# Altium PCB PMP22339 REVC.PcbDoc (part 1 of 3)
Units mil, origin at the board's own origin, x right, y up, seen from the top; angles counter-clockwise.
Board outline 4555 x 3750 mil, 4 copper layers (Top Layer, Signal Layer 2, Signal Layer 3, Bottom Layer), stack 62.6 mil thick; 180 components, 83 nets, 384 pads, 132 vias.
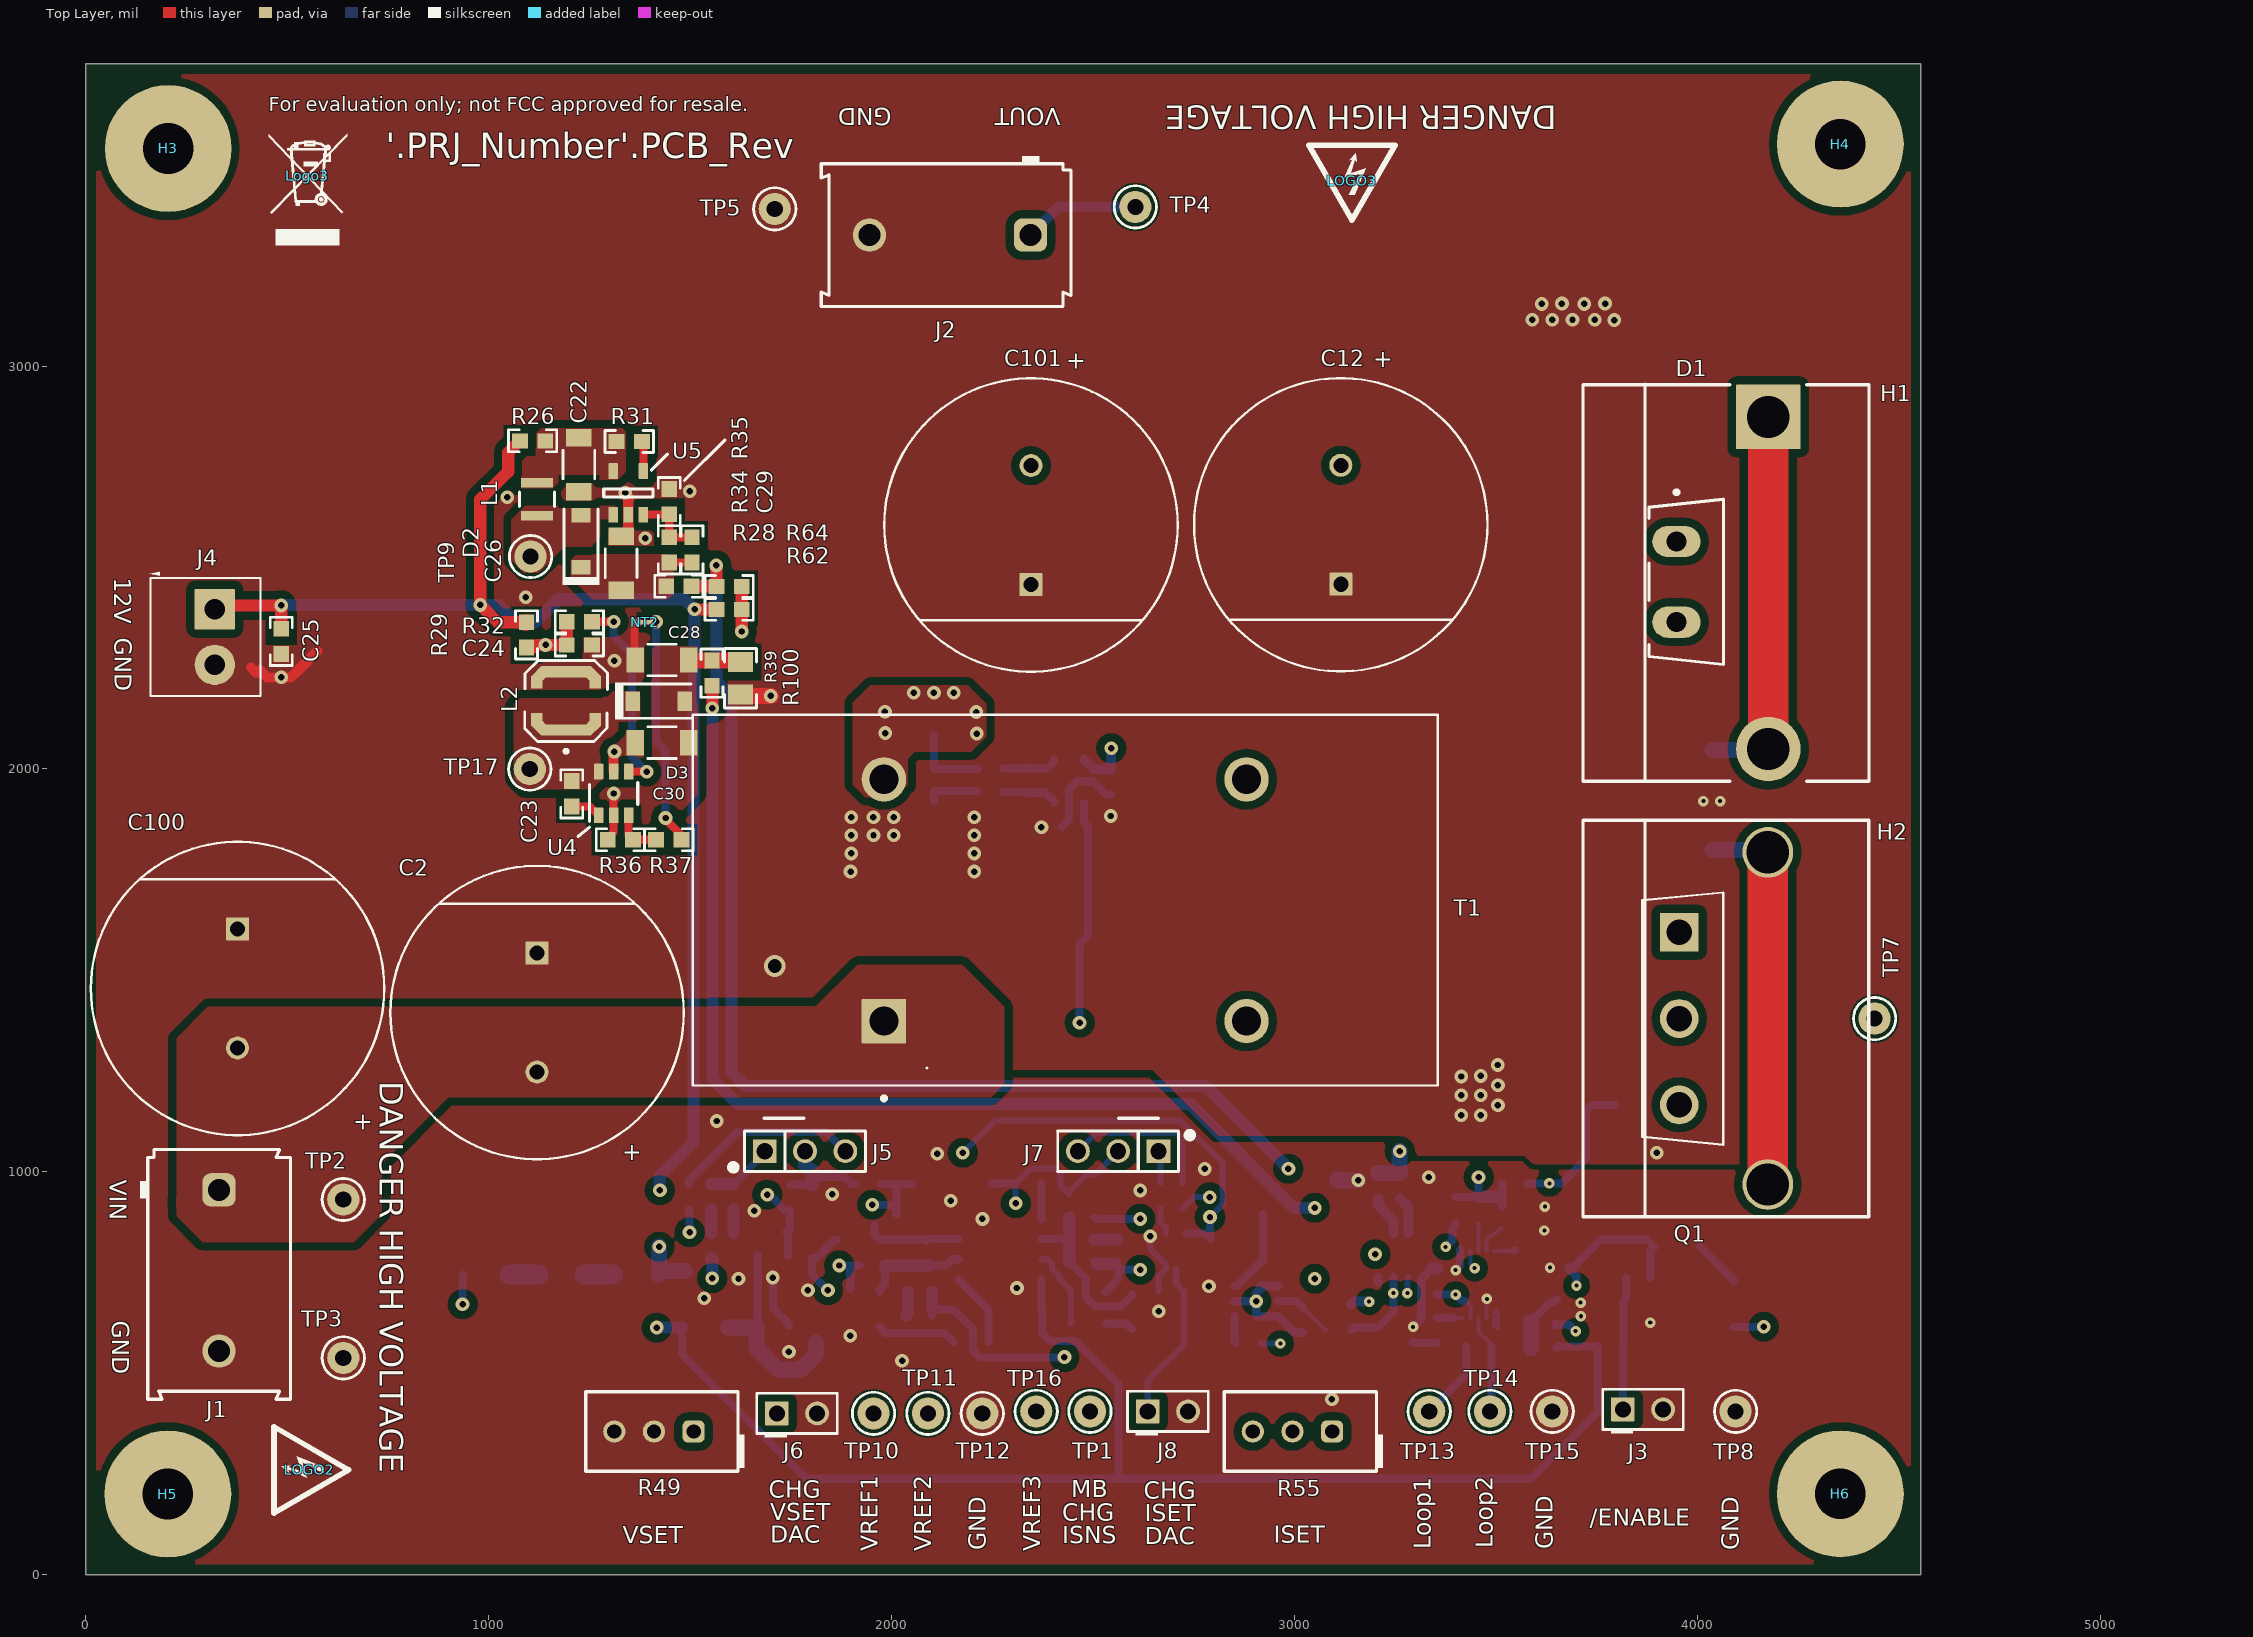
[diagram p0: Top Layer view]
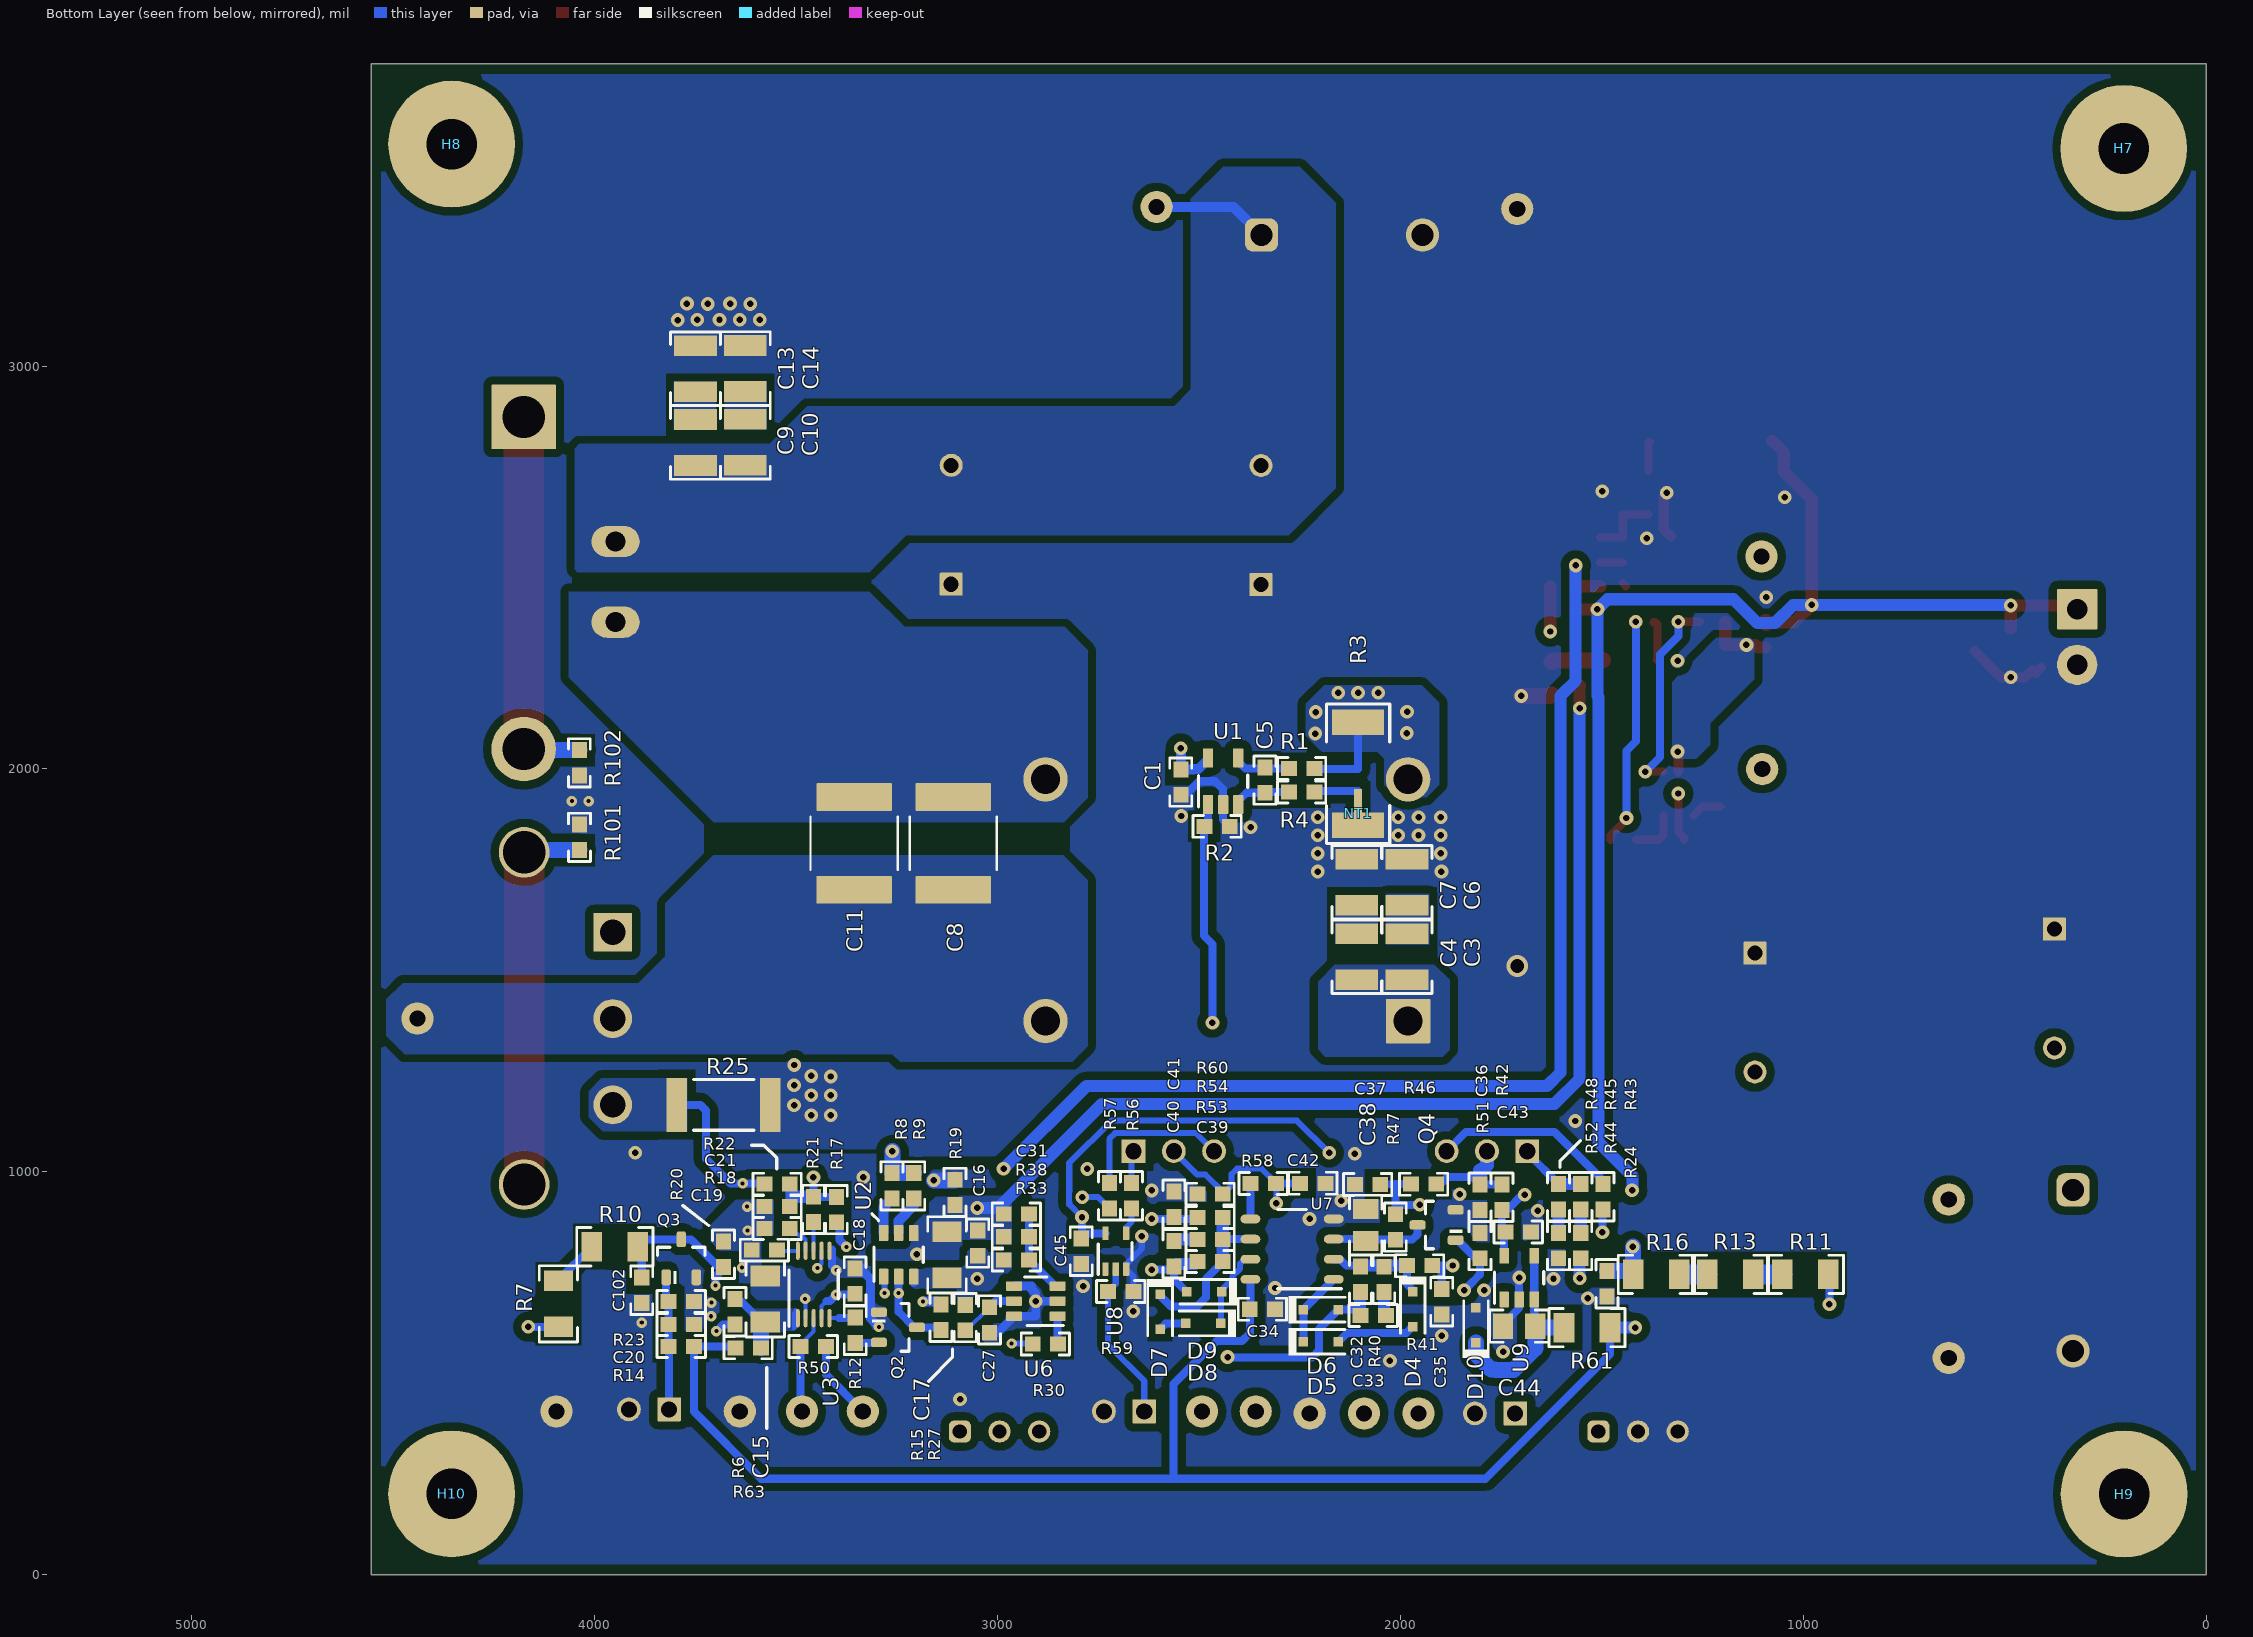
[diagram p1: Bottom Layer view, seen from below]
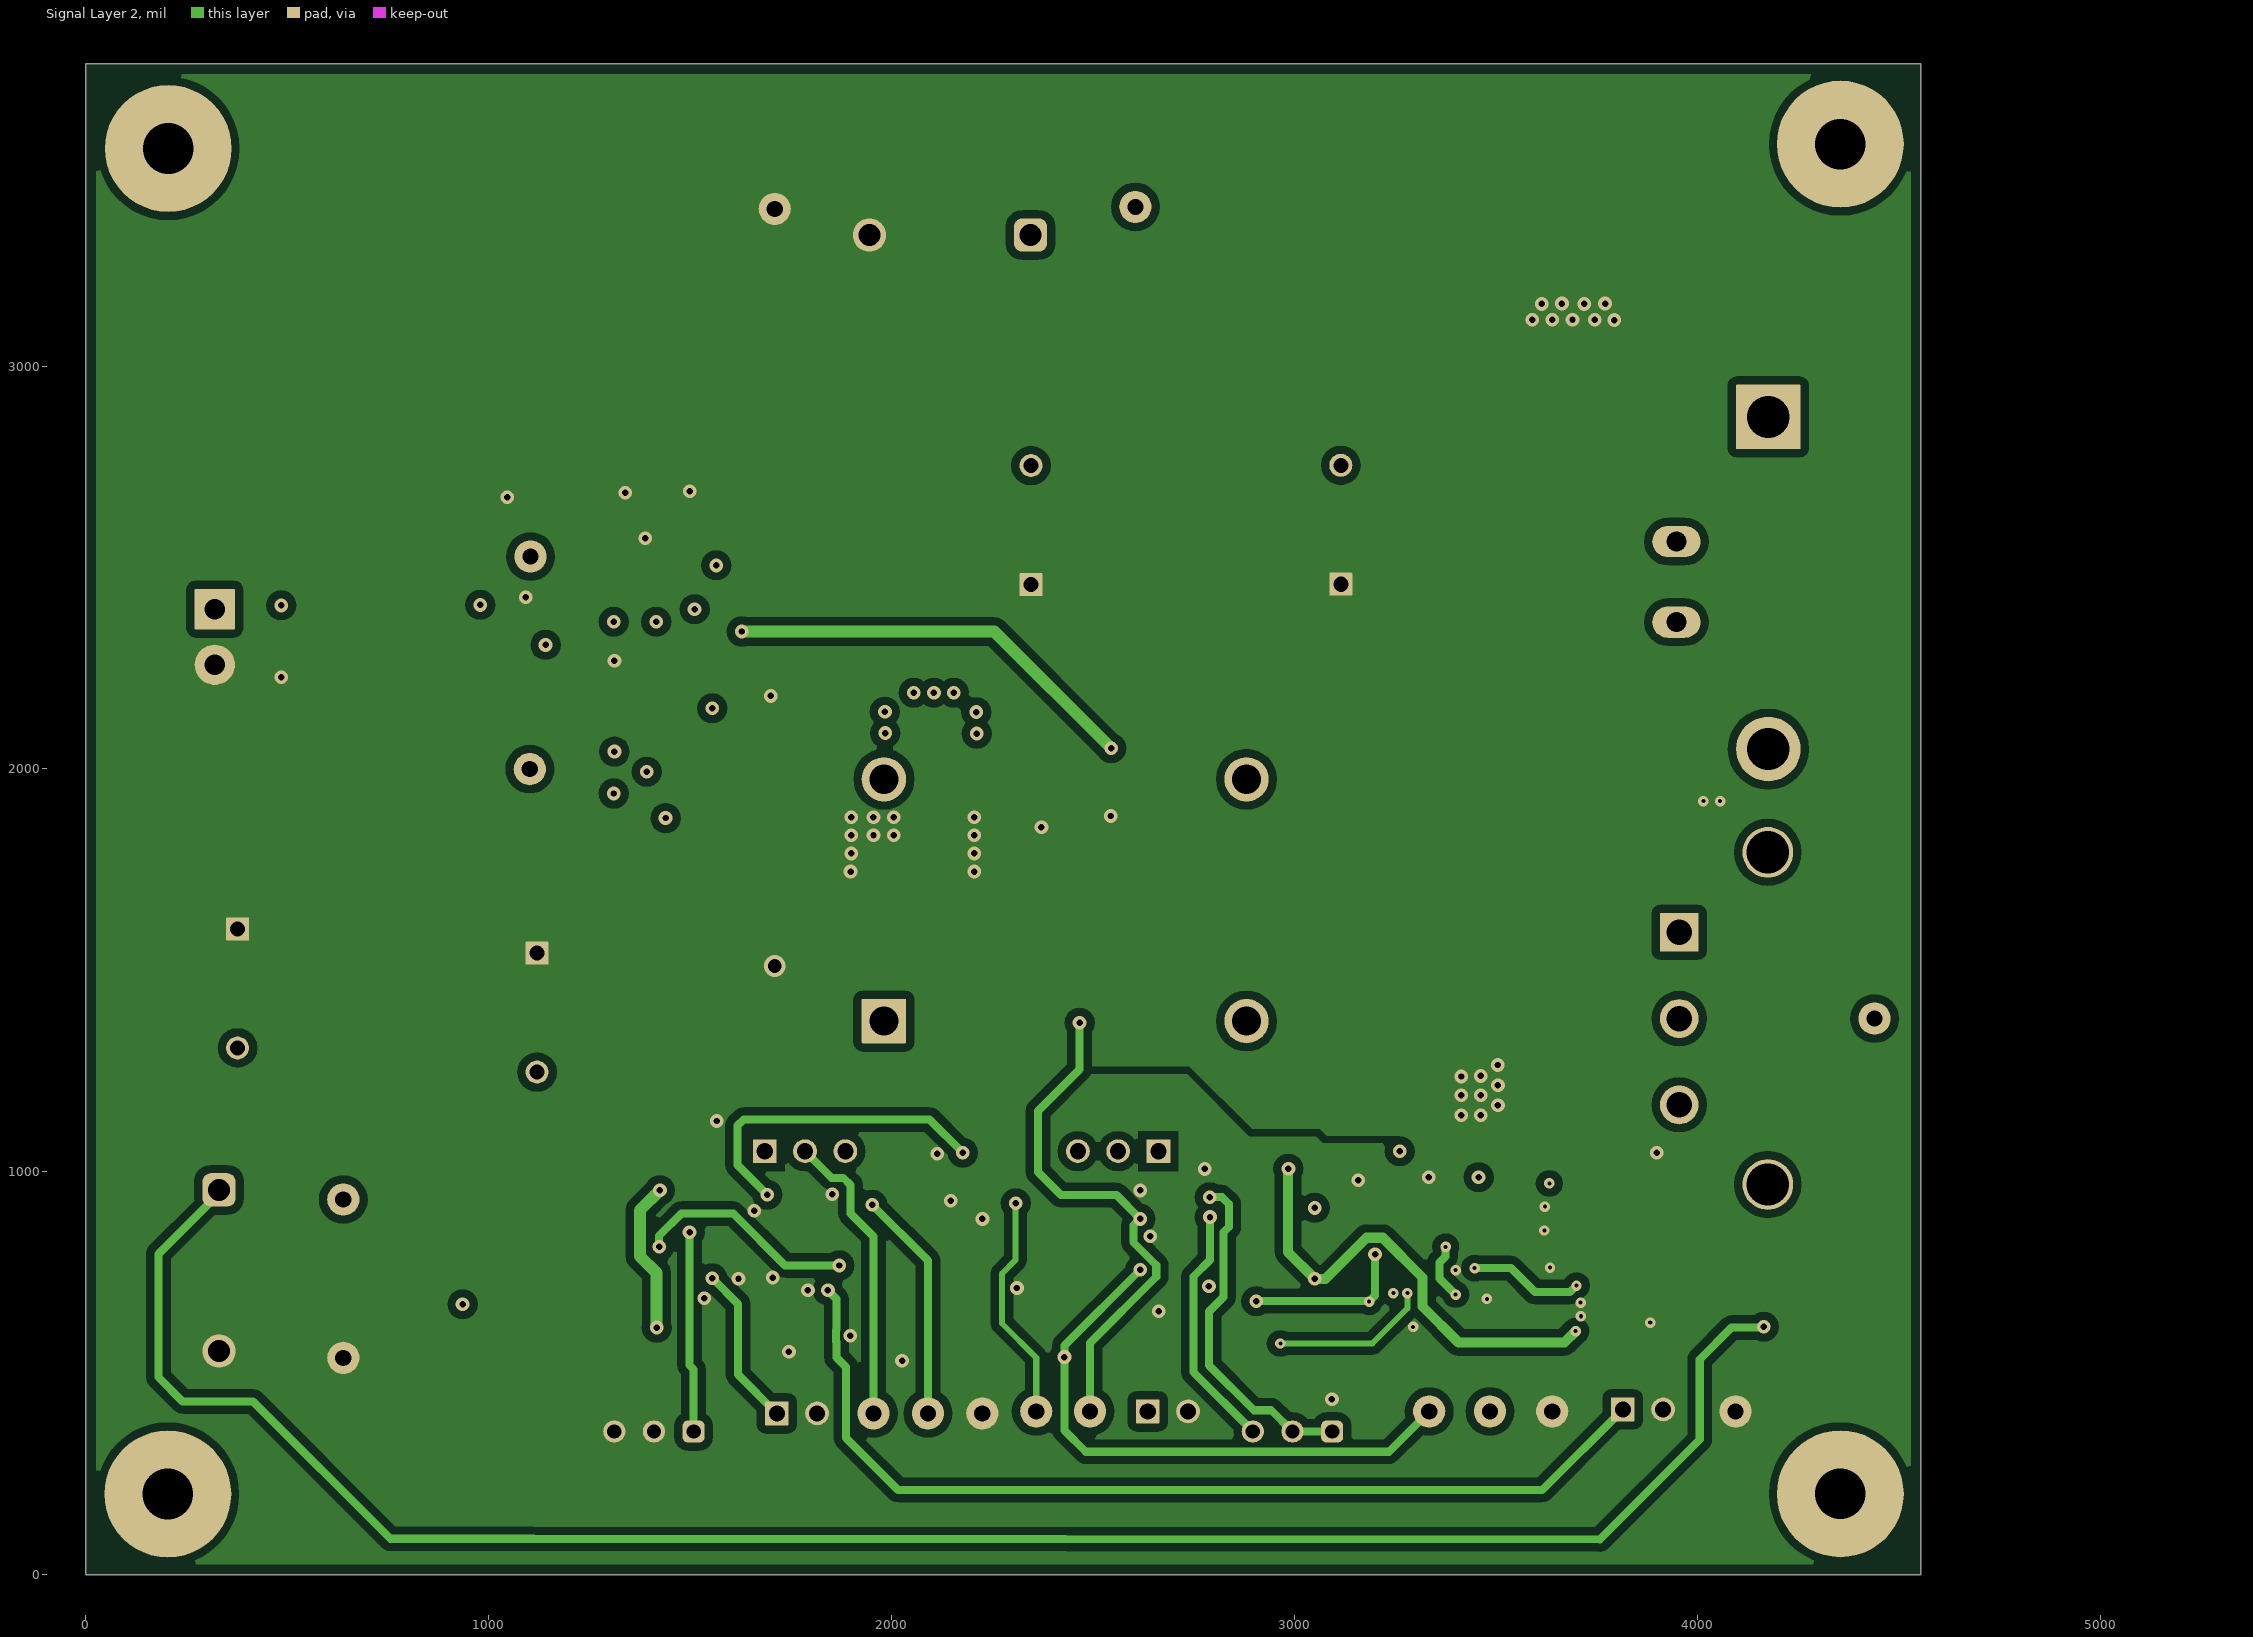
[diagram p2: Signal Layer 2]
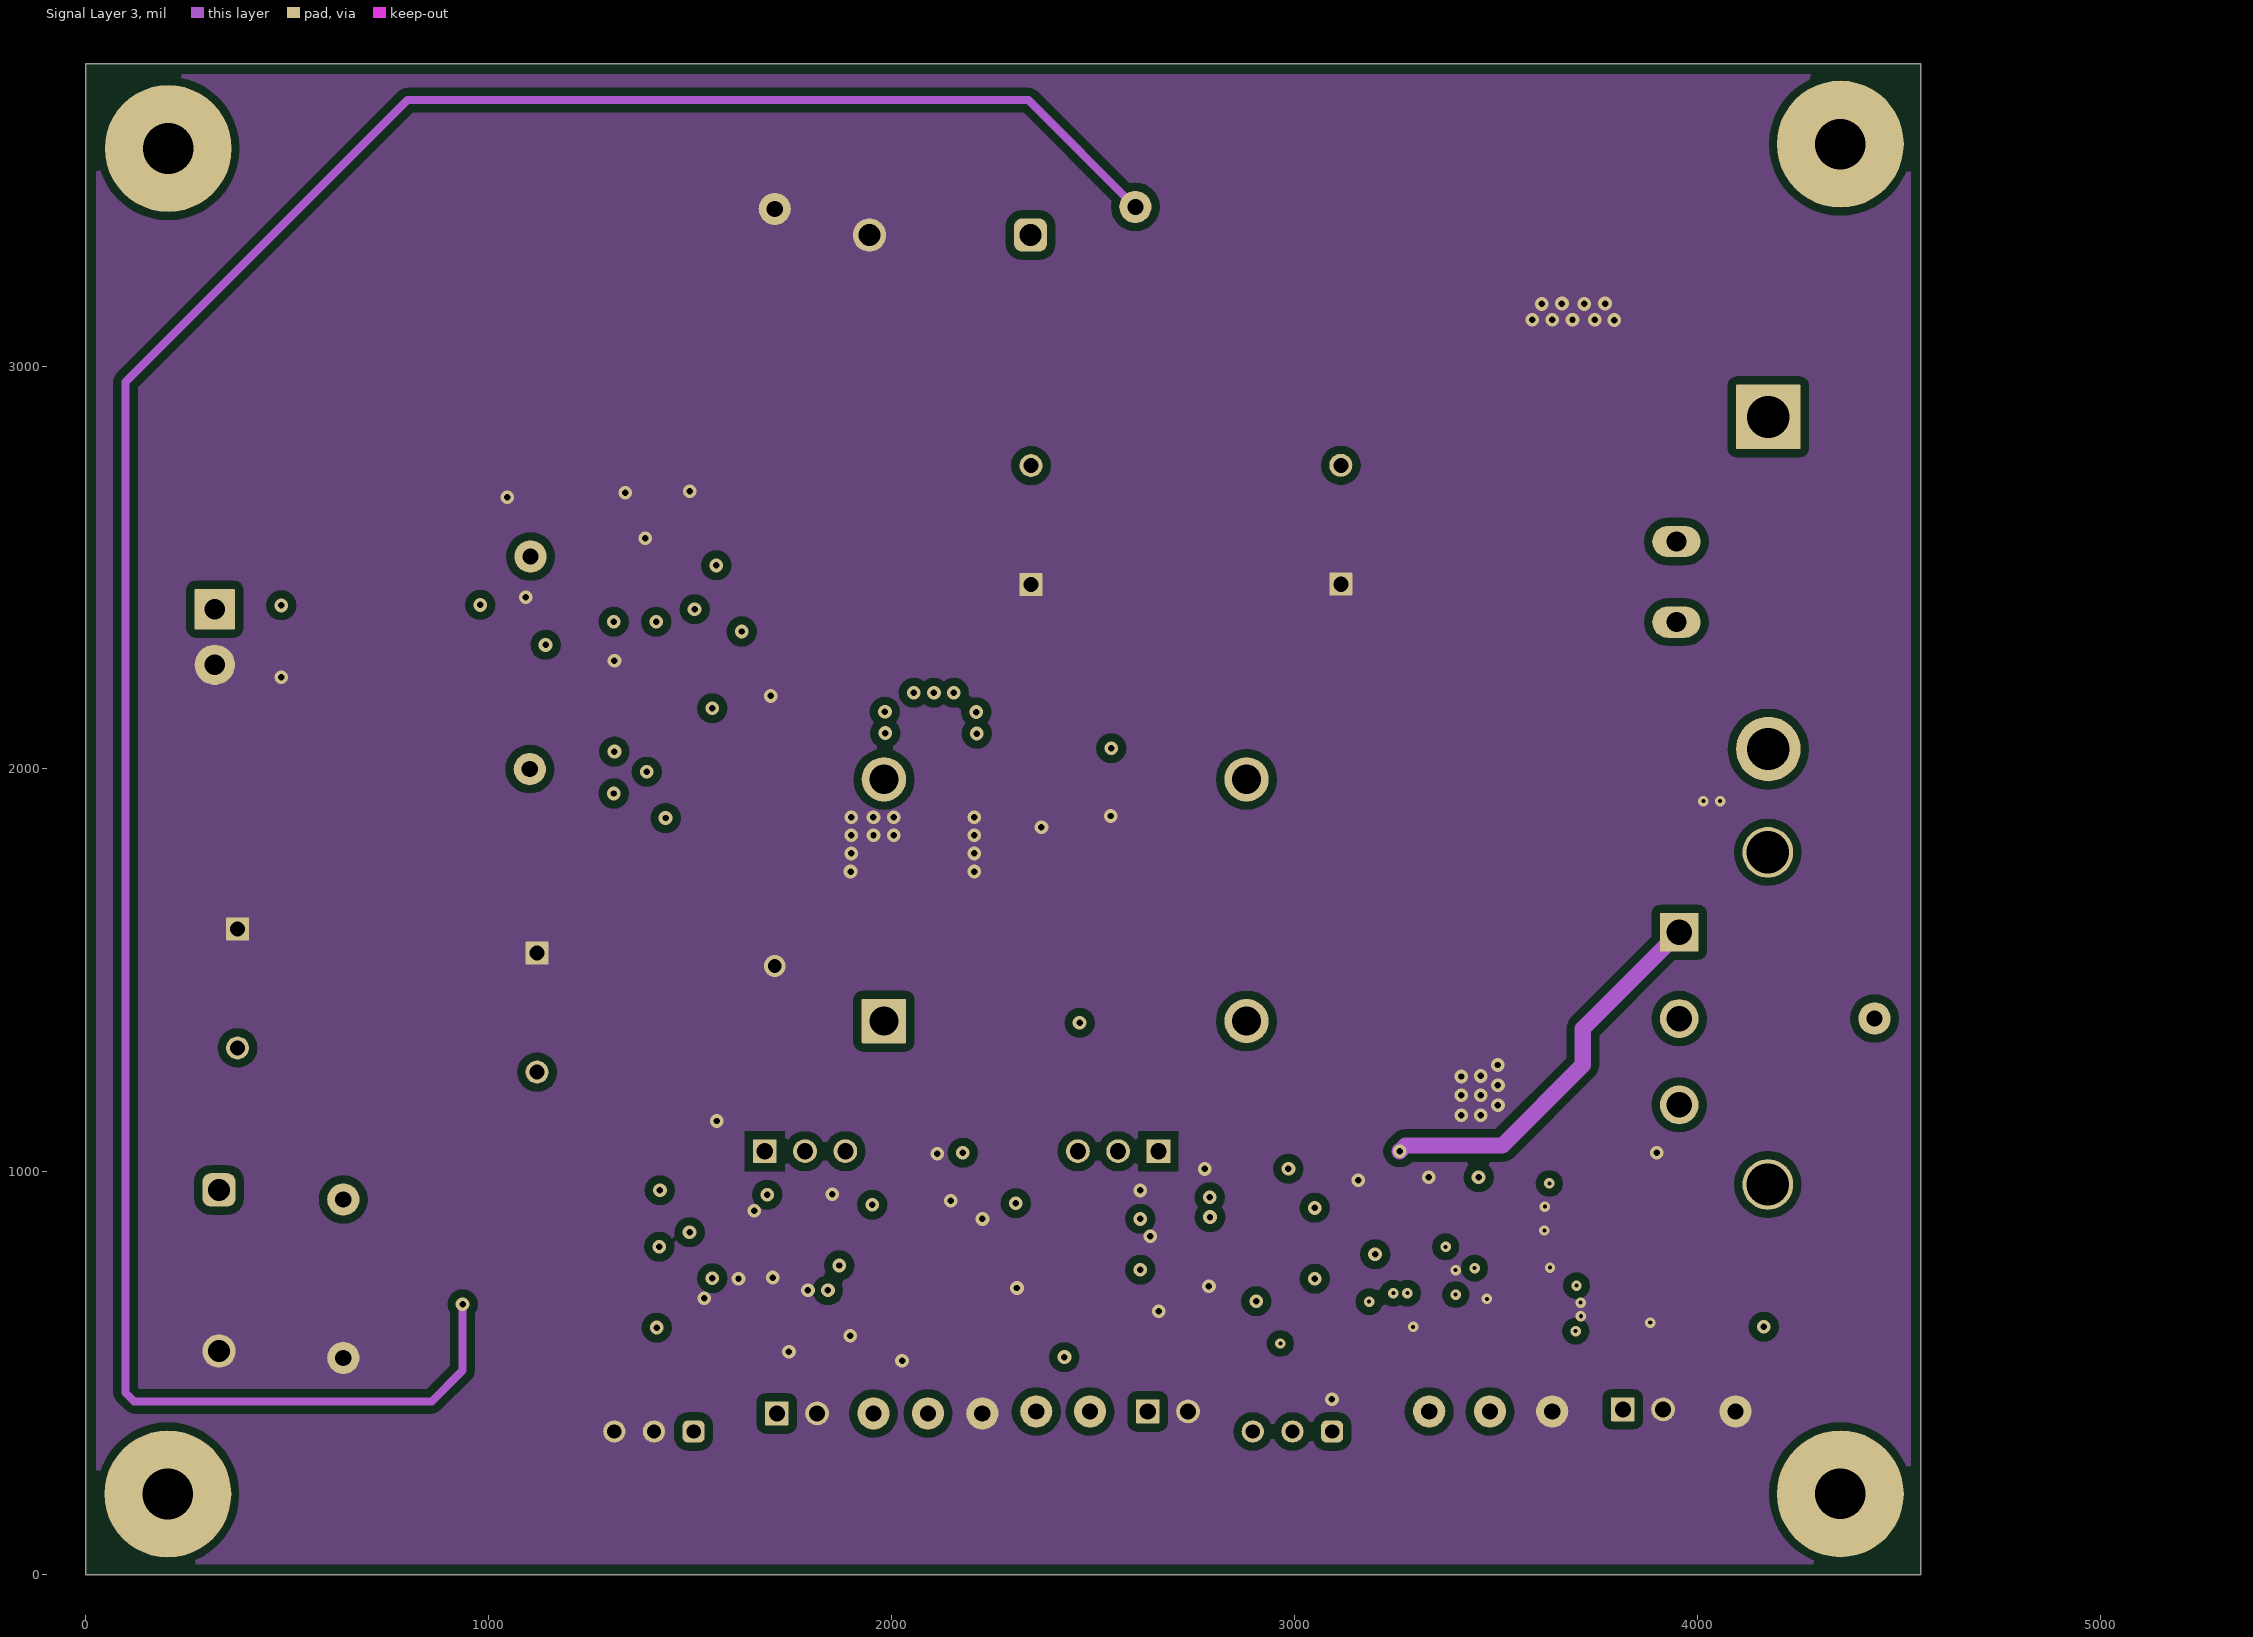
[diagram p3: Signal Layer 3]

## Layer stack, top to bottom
Top Solder: solder mask 0.4, Solder Resist, Dk 3.5
Top Layer: signal copper 2.4
Dielectric1: core 18, FR-4, Dk 4.8
Signal Layer 2: signal copper 2.4
Dielectric 2: prepreg 17, Dk 4.2
Signal Layer 3: signal copper 2.4
Dielectric 3: core 18, Dk 4.2
Bottom Layer: signal copper 2.4
Bottom Solder: solder mask 0.4, Solder Resist, Dk 3.5

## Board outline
0,0 0,3750 4555,3750 4555,0

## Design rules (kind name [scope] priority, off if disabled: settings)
AcuteAngle [All] p1: minimum=4.50000000000000E+0001 checktracksonly=FALSE
AssemblyTestPointUsage [All] p1: valid=2
BoardOutlineClearance BoardOutlineClearance_MountingHoles [OnCopper and InComponentClass('Mounting Holes')] p1: gap=39.37 ignorepadtopadclearanceinfootprint=FALSE
BoardOutlineClearance BoardOutlineClearance_Poly [OnCopper and IsPoly] p2: gap=25 ignorepadtopadclearanceinfootprint=FALSE
BoardOutlineClearance [OnCopper and Not InComponentClass('Logo') and not InComponentClass('FiducialMark') and not InRegion(1000,500,4000,800) and not InPoly] p3: gap=75 ignorepadtopadclearanceinfootprint=FALSE
Clearance Clearance_Keepouts [((IsTrack Or IsArc) And Not InPoly) And IsFree and IsKeepOut vs ((IsTrack Or IsArc) And Not InPoly) And IsFree and IsKeepOut] p1: gap=0 ignorepadtopadclearanceinfootprint=FALSE
Clearance Clearance_Poly [InPolygon] p2: gap=20 ignorepadtopadclearanceinfootprint=TRUE
Clearance Clearance_FiducialMark [IsKeepOut and InComponentClass('FiducialMark') vs IsPad and InComponentClass('FiducialMark')] p3: gap=0 ignorepadtopadclearanceinfootprint=FALSE
Clearance [All] p4: gap=7.87 ignorepadtopadclearanceinfootprint=TRUE
ComponentClearance ComponentClearance_MountingHoles_FiducialMarks [InComponentClass('Mounting Holes') vs InComponentClass('FiducialMark')] p1: gap=50 collisioncheckmode=3 verticalgap=10 showdistances=FALSE
ComponentClearance ComponentClearance_Shunt [InComponentClass('Header') vs InComponentClass('Shunt')] p2: gap=0 collisioncheckmode=3 verticalgap=0 showdistances=FALSE
ComponentClearance ComponentClearance_Logo [InComponentClass('Logo')] p3: gap=25 collisioncheckmode=3 verticalgap=10 showdistances=FALSE
ComponentClearance ComponentClearance_ScrewToNut [(HasFootprint('NY PMS 440 0025 PH')) vs (HasFootprint('Keystone_1902C'))] p4: gap=5 collisioncheckmode=3 verticalgap=10 showdistances=FALSE
ComponentClearance ComponentClearance_MountingHoles [InComponentClass('Mounting Holes')] p5: gap=100 collisioncheckmode=3 verticalgap=100000 showdistances=FALSE
ComponentClearance ComponentClearance_SmallPassives [HasFootprint('0201*') or HasFootprint('0402*') or HasFootprint('0508') or HasFootprint('0603*') or HasFootprint('0612') or HasFootprint('0805*') or HasFootprint('0815*') or HasFootprint('0830*') or HasFootprint('1206*') or HasFootprint('1210*') or HasFootprint('1808*') or HasFootprint('1812*') or HasFootprint('1825*') or HasFootprint('2010*') or HasFootprint('2220*') or HasFootprint('2225*') or HasFootprint('2512*') or HasFootprint('2728*') or HasFootprint('3518*') vs HasFootprint('0201*') or HasFootprint('0402*') or HasFootprint('0508') or HasFootprint('0603*') or HasFootprint('0612') or HasFootprint('0805*') or HasFootprint('0815*') or HasFootprint('0830*') or HasFootprint('1206*') or HasFootprint('1210*') or HasFootprint('1808*') or HasFootprint('1812*') or HasFootprint('1825*') or HasFootprint('2010*') or HasFootprint('2220*') or HasFootprint('2225*') or HasFootprint('2512*') or HasFootprint('2728*') or HasFootprint('3518*')] p6: gap=14.96 collisioncheckmode=3 verticalgap=10 showdistances=FALSE
ComponentClearance ComponentClearance_THtoSMT [IsThruComponent vs IsSMTComponent] p7: gap=40 collisioncheckmode=3 verticalgap=30 showdistances=FALSE
ComponentClearance ComponentClearance_THtoTH [IsThruComponent vs IsThruComponent] p8: gap=30 collisioncheckmode=3 verticalgap=30 showdistances=FALSE
ComponentClearance [All] p9: gap=25 collisioncheckmode=3 verticalgap=10 showdistances=FALSE
DiffPairsRouting [All] p1: maxlimit=100 minlimit=10 mostfreqgap=10 toplayer_minwidth=15 toplayer_maxwidth=15 toplayer_prefwidth=15 midlayer1_minwidth=15 midlayer1_maxwidth=15 midlayer1_prefwidth=15 midlayer2_minwidth=15 midlayer2_maxwidth=15 midlayer2_prefwidth=15 bottomlayer_minwidth=15 bottomlayer_maxwidth=15 bottomlayer_prefwidth=15 maxuncoupledlength=1000
FabricationTestPointUsage TestPointUsage [All] p1: valid=2 allowmultiple=FALSE
FabricationTestpoint Testpoint [All] p1: side=3 testpointundercomponent=TRUE minsize=40 maxsize=100 preferedsize=60 minholesize=0 maxholesize=40 preferedholesize=32 testpointgrid=1 allowsidetop=TRUE allowsidebottom=TRUE usegrid=TRUE gridtolerance=0.01
FanoutControl Fanout_LCC [IsLCC] p1: bgadir=Out bgaviamode=Centered fanoutstyle=Auto fanoutdirection=Alternating viagrid=1 // Fanout_LCC (Default Rule)
FanoutControl Fanout_BGA [IsBGA] p2: bgadir=Out bgaviamode=Centered fanoutstyle=Auto fanoutdirection=Alternating viagrid=1 // Fanout_BGA (Default Rule)
FanoutControl Fanout_Default [All] p4: bgadir=Out bgaviamode=Centered fanoutstyle=Auto fanoutdirection=Alternating viagrid=1 // Fanout_Default (Default Rule)
FanoutControl Fanout_Small [(CompPinCount < 5)] p5: bgadir=Out bgaviamode=Centered fanoutstyle=Auto fanoutdirection=OutThenIn viagrid=1 // Fanout_Small (Default Rule)
Height [All] p1: minheight=0 maxheight=2500 prefheight=500
HoleSize [All] p1: absolutevalues=TRUE maxlimit=500 minlimit=7.87 maxpercent=80.000 minpercent=20.000
MinimumAnnularRing MinimumAnnularRing_ThermalPadVias [IsVia and InAnyComponent] p1: minimumring=5.91
MinimumAnnularRing [All] p2: minimumring=7.87
MinimumSolderMaskSliver MinimumSolderMaskSliver_Logo [InComponentClass('Logo') vs InComponentClass('Logo')] p1: minsoldermaskwidth=0.7
MinimumSolderMaskSliver [All] p2: minsoldermaskwidth=3.94
PlaneConnect [All] p1: planeconnectstyle=Direct reliefexpansion=10 reliefentries=4 reliefconductorwidth=10 reliefairgap=10
PolygonConnect [All] p1: connectstyle=Direct reliefconductorwidth=10 reliefentries=4 polygonreliefangle="90 Angle" airgapwidth=10
RoutingVias ThermalPadVias [IsVia and InAnyComponent] p1: holewidth=7.87 width=19.68 viastyle="Through Hole" minholewidth=7.87 minwidth=19.68 maxholewidth=12.99 maxwidth=23.62
RoutingVias [All] p2: holewidth=16 width=34 viastyle="Through Hole" minholewidth=7.87 minwidth=26 maxholewidth=40 maxwidth=65
SilkToBoardRegionClearance [Not ((IsComment or IsDesignator) And (Hide <> 'False')) and not InRegion(1000,500,4000,800)] p1:
SilkToSilkClearance SilkToSilkClearance_Pb-FreeLogo [(HasFootprint('Pb-Free_Overlay_Medium') OR HasFootprint('Pb-Free_Overlay_Small')) vs (HasFootprint('Pb-Free_Overlay_Medium') OR HasFootprint('Pb-Free_Overlay_Small'))] p1: silktosilkclearance=0
SilkToSilkClearance [All] p2: silktosilkclearance=0
SilkToSolderMaskClearance SilkToComponentPadClearance [(IsPad or IsFill or IsRegion) and InAnycomponent] p1: minsilkscreentomaskgap=0 clearancetoexposedcopper=TRUE
SilkToSolderMaskClearance "Silk to Solder Mask Opening" [All] p2: minsilkscreentomaskgap=0 clearancetoexposedcopper=FALSE
SolderMaskExpansion [All] p1: expansion=1.97
UnRoutedNet [All] p1: checkbadconnections=TRUE
Width [All] p1: maxlimit=100 minlimit=6 preferedwidth=10 checkconnectedcopper=TRUE
13 further rules are at their usual default settings.

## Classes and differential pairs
component class Header: J3 J5 J6 J7 J8
component class "PMP22339 REVC sheet1": C1 C2 C3 C4 C5 C6 C7 C8 C9 C10 C11 C12 C13 C14 C15 C16 C17 C18 C19 C20 C21 C22 C23 C24 C25 C26 C27 C28 C29 C30 C31 C100 C101 C102 D1 D2 D3 H1 H2 J1 J2 J3 J4 L1 L2 LOGO2 Logo2 Logo3 NT1 NT2 Q1 Q2 Q3 R1 R2 R3 R4 R6 R7 R8 R9 R10 R11 R12 R13 R14 R15 R16 R17 R18 R19 R20 R21 R22 R23 R24 R25 R26 R27 R28 R29 R30 R31 R32 R33 R34 R35 R36 R37 R38 R39 R62 R63 R64 R100 R101 R102 T1 TP1 TP2 TP3 TP4 TP5 TP7 TP8 TP9 TP17 U1 U2 U3 U4 U5 U6
component class "PMP22339 REVC sheet2": C32 C33 C34 C35 C36 C37 C38 C39 C40 C41 C42 C43 C44 C45 D4 D5 D6 D7 D8 D9 D10 H3 H4 H5 H6 H7 H8 H9 H10 J5 J6 J7 J8 Q4 R40 R41 R42 R43 R44 R45 R46 R47 R48 R49 R50 R51 R52 R53 R54 R55 R56 R57 R58 R59 R60 R61 TP10 TP11 TP12 TP13 TP14 TP15 TP16 U7 U8 U9
component class "Mounting Holes": H3 H4 H5 H6

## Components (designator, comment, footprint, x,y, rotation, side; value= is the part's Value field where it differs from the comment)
C1 "C0603C104K5RACAUTO" 0603 2545.12,1967.39 r90 bottom value=0.1uF
C2 "500LXW47MEFR18X25" FP-500LXW47MEFR18X25_RADIAL-MFG 1120,1395 r270 top value=47µF
C3 "CGA6L1X7T2J104K160AC" 1210_200 1983.42,1533.25 r90 bottom value=0.1uF
C4 "CGA6L1X7T2J104K160AC" 1210_200 2108.42,1533.25 r90 bottom value=0.1uF
C5 "GRM188R71E224KA88D" 0603 2336.14,1972.2 r90 bottom value=0.22uF
C6 "CGA6L1X7T2J104K160AC" 1210_200 1983.42,1718.25 r90 bottom value=0.1uF
C7 "CGA6L1X7T2J104K160AC" 1210_200 2108.42,1718.25 r90 bottom value=0.1uF
C8 "CKG57NX7T2J105M500JJ" FP-CKG57NX7T2J105M500JJ_5750-MFG 3110,1814.9 r90 bottom value=1uF
C9 "CGA6L1X7T2J104K160AC" 1210_200 3750.12,2810.18 r90 bottom value=0.1uF
C10 "CGA6L1X7T2J104K160AC" 1210_200 3626.12,2810.45 r90 bottom value=0.1uF
C11 "CKG57NX7T2J105M500JJ" FP-CKG57NX7T2J105M500JJ_5750-MFG 3356,1815 r90 bottom
C12 "EKXJ451ELL121MM40S" FP-EKXJ451ELL121MM40S_RADIAL-MFG 3115,2605.94 r90 top value=120µF
C13 "CGA6L1X7T2J104K160AC" 1210_200 3750.12,2993.59 r90 bottom value=0.1uF
C14 "CGA6L1X7T2J104K160AC" 1210_200 3626.12,2993.96 r90 bottom value=0.1uF
C15 "GRM31MR71H105KA88L" 1206 3576.5,684.17 r90 bottom value=1uF
C16 "C0603C104K5RACAUTO" 0603 3049.16,822.83 r90 bottom value=0.1uF
C17 "GRM31MR71H105KA88L" 1206 3125.39,793.65 r90 bottom value=1uF
C18 "Capacitor" 0603 3353.41,728.66 r90 bottom value=1uF
C19 "Capacitor" 0603 3578.74,805.41 r0 bottom value=0.47uF
C20 "GRM188R71E105KA12D" 0603 3785.12,621.04 r180 bottom value=1uF
C21 "GRM1885C1H101JA01D" 0603 3547.25,914.17 r0 bottom value=100pF
C22 "GRM31CR71E475KA88L" 1206_180 1223.79,2755.32 r270 top value=4.7uF
C23 "GRM188R71E224KA88D" 0603 1206.11,1938.05 r270 top value=0.22uF
C24 "C0603C104K5RACAUTO" 0603 1225.12,2307.58 r180 top value=0.1uF
C25 "C0603C104K5RACAUTO" 0603 485,2316.5 r90 top value=0.1uF
C26 "GRM31CR71E475KA88L" 1206_180 1328.79,2510.45 r90 top value=4.7uF
C27 "C0603C104K5RACAUTO" 0603 3020,632 r90 bottom value=0.1uF
C28 "GRJ31CR71A226KE12L" 1206_190 1430.12,2270.18 r0 top value=22uF
C29 "GRM1885C1H151JA01D" 0603 1504.79,2543.38 r270 top value=150pF
C30 "GRM31CR71E475KA88L" 1206_180 1430.12,2065.18 r0 top value=4.7uF
C31 "C0603C104K5RACAUTO" 0603 2953.17,894.92 r180 bottom value=0.1uF
C32 "GRM1885C1H151JA01D" 0603 2098.9,733.27 r270 bottom value=150pF
C33 "C0603C104K5RACAUTO" 0603 2067.4,642.82 r180 bottom value=0.1uF
C34 "C0603C104K5RACAUTO" 0603 2342.35,658.68 r0 bottom value=0.1uF
C35 "GRM188R71H473KA61D" 0603 1897.42,677.38 r270 bottom value=0.047uF
C36 "GRM188R71E105KA12D" 0603 1802.4,936.84 r270 bottom value=1uF
C37 "GRM188R71E105KA12D" 0603 2081.47,968.34 r0 bottom value=1uF
C38 "GRM21BR71E475KA73L" 0805_HV 2086.1,867.82 r90 bottom value=4.7uF
C39 "GRM1885C1H151JA01D" 0603 2472.4,776.83 r0 bottom value=150pF
C40 "C0603C104K5RACAUTO" 0603 2562.4,796.5 r90 bottom value=0.1uF
C41 "GRM1885C1H100JA01D" 0603 2562.4,919.12 r90 bottom value=10pF
C42 "GRM188R71E105KA12D" 0603 2217.4,971.29 r180 bottom value=1uF
C43 "C1608X7R1H474K080AC" 0603 1707.4,850.24 r180 bottom value=0.47uF
C44 "GRM21BR71E475KA73L" 0805_HV 1705.14,616.64 r0 bottom value=4.7uF
C45 "C0603C104K5RACAUTO" 0603 2792.19,802.81 r90 bottom value=0.1uF
C100 "500LXW47MEFR18X25" FP-500LXW47MEFR18X25_RADIAL-MFG 376.58,1455 r270 top value=47µF
C101 "EKXJ451ELL121MM40S" FP-EKXJ451ELL121MM40S_RADIAL-MFG 2346,2605.18 r90 top value=120µF
C102 "C0603C104K5RACAUTO" 0603 3883.19,705.84 r90 bottom value=0.1uF
D1 "C4D05120A" FP-C6D10065A_TO220-2-MFG 3972.38,2464.18 r0 top value="1.2 KV"
D2 "MBR0530T1G" SOD-123 1229.05,2564.83 r90 top value=30V
D3 "MBR0530T1G" SOD-123 1421.97,2168.05 r0 top value=30V
D4 "BAT54HT1G" SOD-323 1969.64,659.09 r270 bottom value=30V
D5 "MMSZ5230BS-7-F" SOD-323 2197.4,577.82 r180 bottom value=4.7V
D6 "BAT54HT1G" SOD-323 2197.4,657.82 r180 bottom value=30V
D7 "BAT54HT1G" SOD-323 2596.48,652.82 r270 bottom value=30V
D8 "MMSZ5230BS-7-F" SOD-323 2489.12,623.44 r0 bottom value=4.7V
D9 "BAT54HT1G" SOD-323 2486.94,701.82 r0 bottom value=30V
D10 "MMSZ5230BS-7-F" SOD-323 1812.4,619.27 r90 bottom value=4.7V
H1 "OMNI-220-18-25-1C" FP-OMNI-220-18-25-1C_PTH_TO220_HEATSINK-MFG 4071,2461.38 r270 top
H2 "OMNI-UNI-27-25" HSINK_OMNI-UNI-18-25 4175.12,1380.54 r270 top
H3 "NY PMS 440 0025 PH" "NY PMS 440 0025 PH" 204.47,3540 r0 top locked
H4 "NY PMS 440 0025 PH" "NY PMS 440 0025 PH" 4355,3550.76 r0 top locked
H5 "NY PMS 440 0025 PH" "NY PMS 440 0025 PH" 203.45,200 r0 top locked
H6 "NY PMS 440 0025 PH" "NY PMS 440 0025 PH" 4355,200.49 r0 top locked
H7 "1902C" Keystone_1902C 204.47,3540 r180 bottom locked
H8 "1902C" Keystone_1902C 4355,3550.76 r180 bottom locked
H9 "1902C" Keystone_1902C 203.45,200 r180 bottom locked
H10 "1902C" Keystone_1902C 4355,200.49 r180 bottom locked
J1 "282843-2" TE_282843-2 330.71,755 r270 top
J2 "282843-2" TE_282843-2 2145,3325 r180 top
J3 "PEC02SAAN" CONN_PEC02SAAN 3865.12,410.18 r0 top
J4 "ED555/2DS" TERM_BLK_ED555-2DS 320,2396.39 r270 top
J5 "PEC03SAAN" CONN_PEC03SAAN 1785.12,1050.91 r0 top
J6 "PEC02SAAN" CONN_PEC02SAAN 1765.12,400.18 r0 top
J7 "PEC03SAAN" CONN_PEC03SAAN 2562.4,1050.91 r180 top
J8 "PEC02SAAN" CONN_PEC02SAAN 2685.89,405.18 r0 top
L1 "CBC2518T100M" CBC2518 1120.09,2669.22 r270 top value=10uH
L2 "LPS4018-333MLB" LPS4018 1191.97,2168.84 r90 top value=33uH
LOGO2 "DANGER HIGH VOLTAGE" IEC_HighVoltage_Small 555,260 r270 top
Logo2 "FCC disclaimer" FCC_disclaimer 1177.16,4463.7 r90 top
LOGO3 "DANGER HIGH VOLTAGE" IEC_HighVoltage_Small 3142.62,3459.6 r180 top (schematic designator LOGO2)
Logo3 "WEEE logo" WEEE_Minimum 550,3471.94 r0 top
NT1 "Net-Tie" Net-Tie_20milWide_60milLong 2105.12,1889.68 r90 bottom net-tie
NT2 "Net-Tie" Net-Tie_10milWide_30milLong 1386.95,2363.98 r180 top net-tie
Q1 "IMW120R140M1HXKSA1" FP-IMW120R140M1HXKSA1_TO247-3-MFG 3963.88,1380.18 r0 top value="1.2 KV"
Q2 "MMBT2907ALT1G" SOT-23 3247.18,613.65 r180 bottom value="60 V"
Q3 "2N7002P,215" SOT-23 3785.12,785.04 r90 bottom value=60V
Q4 "2N7002P,215" SOT-23 1910.16,867.82 r0 bottom value=60V
R1 "CRCW060310R0FKEA" 0603 2245.12,2000.72 r0 bottom value=10.0
R2 "CRCW060349K9FKEA" 0603 2455.12,1857.39 r0 bottom value=49.9k
R3 "CSRN2512FT50L0" CSRN2512 2105.12,1988.13 r90 bottom value=0.05
R4 "CRCW060310R0FKEA" 0603 2245.12,1942.39 r0 bottom value=10.0
R6 "CRCW060310R0FKEA" 0603 3651.5,652.5 r90 bottom value=10.0
R7 "CRCW1206499KFKEA" 1206 4090,672.12 r270 bottom value=499k
R8 "CRCW060310R0FKEA" 0603 3262.2,964.98 r90 bottom value=10.0
R9 "CRCW06030000Z0EA" 0603 3207.99,964.98 r90 bottom value=0
R10 "CRCW1206499KFKEA" 1206 3950.12,813.88 r0 bottom value=499k
R11 "CRCW1206499KFKEA" 1206 995,745.18 r180 bottom value=499k
R12 "CRCW0603649RFKEA" 0603 3353.16,606.63 r270 bottom value=649
R13 "CRCW1206499KFKEA" 1206 1181,745.18 r0 bottom value=499k
R14 "CRCW060310K0FKEA" 0603 3785.12,566.04 r180 bottom value=10.0k
R15 "CRCW0603402RFKEA" 0603 3140.12,638.68 r270 bottom value=402
R16 "CRCW1206590KFKEA" 1206 1364.8,745.18 r180 bottom value=590k
R17 "CRCW060366K5FKEA" 0603 3400.12,906 r270 bottom value=66.5k
R18 "CRCW0603169KFKEA" 0603 3547.25,859.17 r180 bottom value=169k
R19 "CRCW06030000Z0EA" 0603 3105.7,948.65 r270 bottom value=0
R20 "CRCW06033K74FKEA" 0603 3680.12,795.18 r270 bottom value=3.74k
R21 "CRCW06030000Z0EA" 0603 3457.28,906.32 r270 bottom value=0
R22 "Resistor" 0603 3547.25,969.17 r0 bottom value=1.00k
R23 "CRCW060320K0FKEA" 0603 3785.12,678.36 r0 bottom value=20.0k
R24 "CRCW060310K0FKEA" 0603 1487,722 r90 bottom value=10.0k
R25 "WSL2512R0330FEA18" 2512 3680,1165.77 r0 bottom value=0.033
R26 "CRCW06030000Z0EA" 0603 1108.79,2814.38 r0 top value=0
R27 "CRCW06030000Z0EA" 0603 3080.12,638.12 r90 bottom value=0
R28 "CRCW06030000Z0EA" 0603 1472.14,2453.38 r0 top value=0
R29 "CRCW06030000Z0EA" 0603 1093.79,2332.48 r270 top value=0
R30 "CRCW06030000Z0EA" 0603 2881,572.63 r180 bottom value=0
R31 "CRCW0603100KFKEA" 0603 1348.79,2812.82 r180 top value=100k
R32 "CRCW0603100KFKEA" 0603 1225.12,2365.18 r0 top value=100k
R33 "CRCW060352K3FKEA" 0603 2953.17,780.86 r0 bottom value=52.3k
R34 "CRCW0603182KFKEA" 0603 1448.14,2543.38 r270 top value=182k
R35 "CRCW060313K3FKEA" 0603 1448.14,2663.38 r270 top value=13.3k
R36 "CRCW06031K00FKEA" 0603 1326.97,1824.03 r0 top value=1.00k
R37 "CRCW06035K49FKEA" 0603 1446.97,1824.03 r0 top value=5.49k
R38 "CRCW06031K00FKEA" 0603 2953.17,838.56 r180 bottom value=1.00k
R39 "CRCW06030000Z0EA" 0603 1553.96,2237.84 r90 top value=0
R40 "CRCW0603274KFKEA" 0603 2041.2,732.82 r270 bottom value=274k
R41 "CRCW060310K0FKEA" 0603 1952.4,766.82 r0 bottom value=10.0k
R42 "CRCW060321K5FKEA" 0603 1747.4,936.84 r270 bottom value=21.5k
R43 "CRCW060316K5FKEA" 0603 1497.4,937.82 r90 bottom value=16.5k
R44 "CRCW060351K1FKEA" 0603 1552.4,816.85 r90 bottom value=51.1k
R45 "CRCW0603165RFKEA" 0603 1552.4,937.82 r90 bottom value=165
R46 "CRCW060310K0FKEA" 0603 1942.56,969.11 r0 bottom value=10.0k
R47 "CRCW060310K0FKEA" 0603 2012.66,862.82 r270 bottom value=10.0k
R48 "CRCW060375K0FKEA" 0603 1607.4,937.82 r90 bottom value=75.0k
R49 "PV36W104C01B00" Bourns_PV36W 1410.19,355.18 r180 top value=100k
R50 "CRCW06030000Z0EA" 0603 3457.28,566.04 r0 bottom value=0
R51 "CRCW060320K0FKEA" 0603 1802.4,816.85 r270 bottom value=20.0k
R52 "CRCW06031K18FKEA" 0603 1607.4,816.85 r90 bottom value=1.18k
R53 "CRCW06030000Z0EA" 0603 2472.4,831.5 r0 bottom value=0
R54 "CRCW060310K0FKEA" 0603 2472.4,886.5 r180 bottom value=10.0k
R55 "PV36W104C01B00" Bourns_PV36W 2995.12,355.18 r180 top value=100k
R56 "CRCW06031K91FKEA" 0603 2722.4,940.57 r90 bottom value=1.91k
R57 "CRCW06032K00FKEA" 0603 2667.4,940.57 r90 bottom value=2.00k
R58 "CRCW060310K0FKEA" 0603 2340.64,970.84 r0 bottom value=10.0k
R59 "CRCW060310K0FKEA" 0603 2694.42,702.52 r0 bottom value=10.0k
R60 "CRCW06034K02FKEA" 0603 2472.4,944.27 r180 bottom value=4.02k
R61 "CRCW12061K00FKEA" 1206 1536.94,613.15 r180 bottom value=1.00k
R62 "CRCW06030000Z0EA" 0603 1596.55,2396 r180 top value=0
R63 "CRCW060310R0FKEA" 0603 3619,563 r180 bottom value=10.0
R64 "CRCW06030000Z0EA" 0603 1596.55,2453 r180 top value=0
R100 "CRCW0805499RFKEA" 0805_HV 1625,2225 r270 top value=499
R101 "CRCW06030000Z0EA" 0603 4038,1830 r270 bottom value=0
R102 "CRCW06030000Z0EA" 0603 4038,2015 r90 bottom value=0
T1 "RLTI-1363" FP-RLTI-1363_PTH_1IN85_0IN92-MFG 2431,1674 r0 top
TP1 "5000" Keystone5000 2492.4,405.18 r90 top
TP2 "5000" Keystone5000 639,931 r180 top
TP3 "5001" Keystone5001 639,538 r180 top
TP4 "5000" Keystone5000 2605,3395 r180 top
TP5 "5001" Keystone5001 1710,3390 r0 top
TP7 "5000" Keystone5000 4440,1380.18 r90 top
TP8 "5001" Keystone5001 4095,405.18 r270 top
TP9 "5000" Keystone5000 1103.79,2527 r270 top
TP10 "5000" Keystone5000 1955.12,400.18 r90 top
TP11 "5000" Keystone5000 2090.12,400.18 r90 top
TP12 "5001" Keystone5001 2225.12,400.18 r90 top
TP13 "5003" Keystone5003 3334.46,405.18 r90 top
TP14 "5003" Keystone5003 3485.12,405.18 r90 top
TP15 "5001" Keystone5001 3639.77,405.18 r90 top
TP16 "5000" Keystone5000 2359.05,405.18 r90 top
TP17 "5000" Keystone5000 1101.97,1999.35 r180 top
U1 "INA293A1IDBVR" DBV0005A_M 2440.12,1969.25 r90 bottom
U2 "UCC27531DBVR" DBV0006A_N 3245.39,793.65 r90 bottom
U3 "LM5022QDGSRQ1" DGS0010A_L 3456.5,720.17 r90 bottom
U4 "LMR14203XMKX/NOPB" DDC0006A_N 1310.08,1938.91 r90 top
U5 "LMR64010XMFE/NOPB" DBV0005A_N 1346.39,2685.03 r90 top
U6 "TPS3711DDCR" DDC0006A_N 2905.12,678.68 r0 bottom
U7 "TLC272AIDR" D0008A_L 2268.91,807.82 r0 bottom
U8 "SN74LVC1G34DCKR" DCK0005A_N 2706.53,802.81 r90 bottom
U9 "LM4132AMF-3.0/NOPB" DBV0005A_N 1705.14,737.36 r90 bottom

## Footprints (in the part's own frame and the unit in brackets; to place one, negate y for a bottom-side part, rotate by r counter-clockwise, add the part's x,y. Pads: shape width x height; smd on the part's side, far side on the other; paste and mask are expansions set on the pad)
0603 [mm] "0603 from SM-752 data"
  rect 1x0.95 smd: 1(-0.8,0) 2(0.8,0)
  silkscreen extent -1.52,-0.69 1.52,0.69, body extent -0.87,-0.47 0.87,0.47, height 1
0805_HV [mil] "0805 with 30mil clearance between pads"
  rect 50x63 smd: 1(-40,0) 2(40,0)
  silkscreen extent -74,-40 74,40, body extent -43,-29 43,29, height 57
1206 [mm] "1206 from SM-752 data"
  rect 1.3x1.85 smd: 1(-1.45,0) 2(1.45,0)
  silkscreen extent -2.4,-1.21 2.4,1.21, body extent -1.7,-0.9 1.7,0.9, height 1.35
1206_180 [mm] "1206_180"
  rect 1.1x1.6 smd: 1(-1.7,0) 2(1.7,0)
  silkscreen extent -0.9,-1 0.9,1, body extent -1.75,-0.95 1.75,0.95, height 1.8
1206_190 [mm] "1206_190"
  rect 1.1x1.6 smd: 1(-1.7,0) 2(1.7,0)
  silkscreen extent -0.9,-1 0.9,1, body extent -1.75,-0.95 1.75,0.95, height 1.9
1210_200 [mm] "1210"
  rect 1.3x2.7 smd: 1(-1.45,0) 2(1.45,0)
  silkscreen extent -2.32,-1.57 2.32,1.57, body extent -1.7,-1.35 1.7,1.35, height 2
2512 [mm] "Chip Resistor, Body 6.3x3.2mm, IPC Medium Density"
  rect 1.3x3.4 smd: 1(-2.95,0) 2(2.95,0)
  silkscreen extent -1.9,-1.6 1.9,1.6, body extent -3.22,-1.67 3.22,1.67, height 0.71
Bourns_PV36W [mm] "TH, 3-Leads, Body 9.53x4.83mm, Pitch 2.5mm"
  rrect50% 1.4x1.4 hole 0.9: 1(-2.5,0)
  round 1.4 hole 0.9: 2(0,0) 3(2.5,0)
  silkscreen extent -5.7,-2.5 4.3,2.5, body extent -5.29,-2.49 4.31,2.51, height 11.53
CBC2518 [mm] "Taiyo Yuden"
  rect 0.6x2 smd: 1(-1.05,0) 2(1.05,0)
  silkscreen extent -0.45,-1.1 0.45,1.1, body extent -1.35,-1 1.35,1, height 2
CONN_PEC02SAAN [mm] "SULLINS"
  rrect7% 1.5x1.5 hole 1.016: 1(-1.27,0)
  round 1.5 hole 1.016: 2(1.27,0)
  silkscreen extent -2.54,-1.52 2.54,1.27, body extent -2.54,-1.27 2.54,1.27, height 8.38
CONN_PEC03SAAN [mm] "SULLINS"
  rect 1.5x1.5 hole 1.016: 1(-2.54,0)
  round 1.5 hole 1.016: 2(0,0) 3(2.54,0)
  silkscreen extent -4.72,-1.27 3.81,1.27, body extent -3.84,-1.3 3.84,1.3, height 8.38
CSRN2512 [mm] "STACKPOLE"
  rect 1.6x3.3 smd: 1(-3.25,0) 2(3.25,0)
  silkscreen extent -4.4,-2 4.4,2, body extent -3.27,-1.65 3.27,1.65, height 0.7
D0008A_L [mm] "SOIC, 8-Leads, Body 4.9x3.9mm, Pitch 1.27mm, IPC High Density"
  oval 1.25x0.55 smd: 1(-2.625,1.905) 2(-2.625,0.635) 3(-2.625,-0.635) 4(-2.625,-1.905) 5(2.625,-1.905) 6(2.625,-0.635) 7(2.625,0.635) 8(2.625,1.905)
  silkscreen extent -3.1,-2.5 0.9,2.5, body extent -3,-2.45 3,2.45, height 1.63
DBV0005A_M [mm] "SOT23, 5-Leads, Body 2.9x1.6mm, Pitch 0.95mm, Lead Span 2.8mm, IPC Low Density"
  rrect15% 1.2x0.65 smd: 1(-1.475,0.95) 2(-1.475,0) 3(-1.475,-0.95) 4(1.475,-0.95) 5(1.475,0.95)
  silkscreen extent -1.63,-1.55 0.38,1.55, body extent -1.42,-1.46 1.42,1.46, height 1.09
DBV0005A_N [mm] "SOT23, 5-Leads, Body 2.9x1.6mm, Pitch 0.95mm, Lead Span 2.8mm, IPC Medium Density"
  rrect17% 1x0.6 smd: 1(-1.375,0.95) 2(-1.375,0) 3(-1.375,-0.95) 4(1.375,-0.95) 5(1.375,0.95)
  silkscreen extent -0.25,-1.55 0.25,1.55, body extent -1.42,-1.46 1.42,1.46, height 1.09
DBV0006A_N [mm] "SOT23, 6-Leads, Body 2.9x1.6mm, Pitch 0.95mm, Lead Span 2.8mm, IPC Medium Density"
  rrect17% 1x0.6 smd: 1(-1.375,0.95) 2(-1.375,0) 3(-1.375,-0.95) 4(1.375,-0.95) 5(1.375,0) 6(1.375,0.95)
  silkscreen extent -1.68,-1.55 0.5,1.55, body extent -1.42,-1.46 1.42,1.46, height 1.12
DCK0005A_N [mm] "SOT353, 5-Leads, Body 2x1.3mm, Pitch 0.65mm, Lead Span 2.1mm, IPC Medium Density"
  rrect25% 0.85x0.4 smd: 1(-1.125,0.65) 2(-1.125,0) 3(-1.125,-0.65) 4(1.125,-0.65) 5(1.125,0.65)
  silkscreen extent -1.48,-1.02 0.55,1.1, body extent -1.14,-1 1.14,1, height 0.95
DDC0006A_N [mm]
  rrect17% 1x0.6 smd: 1(-1.375,0.95) 2(-1.375,0) 3(-1.375,-0.95) 4(1.375,-0.95) 5(1.375,0) 6(1.375,0.95)
  silkscreen extent -1.75,-1.52 0.7,1.53, body extent -1.43,-1.48 1.43,1.49, height 0.92
DGS0010A_L [mm] "TSSOP, 10-Leads, Body 3x3mm, Pitch 0.5mm, IPC High Density"
  oval 1.15x0.25 smd: 1(-2.125,1) 2(-2.125,0.5) 3(-2.125,0) 4(-2.125,-0.5) 5(-2.125,-1) 6(2.125,-1) 7(2.125,-0.5) 8(2.125,0) 9(2.125,0.5) 10(2.125,1)
  silkscreen extent -2.65,-1.55 0.9,1.55, body extent -2.45,-1.5 2.45,1.5, height 0.96
FCC_disclaimer [mil]
FP-500LXW47MEFR18X25_RADIAL-MFG [mm] "TH, 2-Leads, Dia 12.5mm, Pin Spacing 5mm"
  rrect7% 1.45x1.45 hole 0.95 paste-1000 mask+0: 1(-3.75,0)
  round 1.45 hole 0.95 paste-1000 mask+0: 2(3.75,0)
  silkscreen extent -9.25,-9.25 9.25,9.25, body extent -9.35,-9.35 9.35,9.35, height 0.25
FP-C6D10065A_TO220-2-MFG [mil]
  rrect100% 120x77.56 hole 50 paste-39370.1 mask+0: 1(-24.26,100) 2(-24.26,-100)
  silkscreen extent -92,-205 92,227, body extent -96,-209 96,209, height 10
FP-CKG57NX7T2J105M500JJ_5750-MFG [mm] "Chip Capacitor, Body 6.0x5.0x5.0mm,"
  rrect6% 1.75x4.75 smd paste+0 mask+0: 1(-2.925,0) 2(2.925,0)
  silkscreen extent -1.68,-2.75 1.68,2.75, body extent -3,-2.5 3,2.5, height 5.5
FP-EKXJ451ELL121MM40S_RADIAL-MFG [mm] "TH, 2-Leads, Dia 18mm, Lead Sapcing 7.5mm"
  rrect7% 1.45x1.45 hole 0.95 paste-1000 mask+0: 1(-3.75,0)
  round 1.45 hole 0.95 paste-1000 mask+0: 2(3.75,0)
  silkscreen extent -9.25,-9.25 9.25,9.25, body extent -9.35,-9.35 9.35,9.35, height 0.25
FP-IMW120R140M1HXKSA1_TO247-3-MFG [mm]
  rrect4% 2.45x2.45 hole 1.6 paste-1000 mask+0: 1(-0.222,5.44)
  round 2.45 hole 1.6 paste-1000 mask+0: 2(-0.222,0) 3(-0.222,-5.44)
  silkscreen extent -2.55,-7.95 2.55,7.95, body extent -2.65,-8.05 2.65,8.05, height 0.25
FP-OMNI-220-18-25-1C_PTH_TO220_HEATSINK-MFG [mm]
  rrect2% 4.07x4.07 hole 2.67 paste-1000 mask+0: 1(-10.47,2.67)
  round 4.07 hole 2.67 paste-1000 mask+0: 2(10.47,2.67)
  silkscreen extent -12.5,-9.02 12.5,9.02, body extent -12.6,-9.12 12.6,9.12, height 0.25
FP-RLTI-1363_PTH_1IN85_0IN92-MFG [mm]
  rrect4% 2.8x2.8 hole 1.85 paste-1000 mask+0: 1(-11.43,-7.62)
  round 2.8 hole 1.85 paste-1000 mask+0: 2(-11.43,7.62) 3(11.43,7.62) 4(11.43,-7.62)
  silkscreen extent -23.49,-12.62 23.49,11.68, body extent -23.59,-11.78 23.59,11.78, height 0.25
HSINK_OMNI-UNI-18-25 [mm] "Heat Sink, 2-Leads, Body 25x18mm"
  round 3.2 hole 2.67: 1(-10.47,0) 2(10.47,0)
  silkscreen extent -12.5,-11.67 12.5,6.36, body extent -12.5,-11.63 12.5,6.4, height 38.1
IEC_HighVoltage_Small [mil]
  silkscreen extent -107,-88 107,97
Keystone5000 [mil] "For Keystone 500x miniature loop terminals"
  round 80 hole 40: 1(0,0)
  silkscreen extent -52,-52 52,52, body extent -49,-49 49,49, height 182
Keystone5001 [mil] "For Keystone 500x miniature loop terminals"
  round 80 hole 40: 1(0,0)
  silkscreen extent -52,-52 52,52, body extent -49,-49 49,49, height 182
Keystone5003 [mil] "For Keystone 500x miniature loop terminals"
  round 80 hole 40: 1(0,0)
  silkscreen extent -52,-52 52,52, body extent -49,-49 49,49, height 182
Keystone_1902C [mil] "Hex Standoff, 4-40 threaded, nylon"
  round 1 on Mech4: 0(0,0)
  body extent -145,-126 146,126, height 501
LPS4018 [mil]
  rect 28x123 smd: 1(-72.5,0) 2(72.5,0)
  rect 35.5x28 smd rot 45: 1(-64,64) 2(64.5,-63.5)
  rect 35.5x28 smd rot 135: 1(-64,-64) 2(64,64)
  rect 31.5x28 smd: 1(-46,72.5) 1(-46,-72.5) 2(46,72.5) 2(46,-72.5)
  silkscreen extent -129,-102 100,102, body extent -81,-81 81,81, height 71
Net-Tie_10milWide_30milLong [mil] "10mil net tie, no solder mask opening, no solder paste"
  rect 30x10 smd paste-5 mask-5: 1(-15,0) 2(15,0)
Net-Tie_20milWide_60milLong [mil] "20mil net tie, no solder mask opening, no solder paste"
  rect 60x20 smd paste-10 mask-10: 1(-30,0) 2(30,0)
"NY PMS 440 0025 PH" [mm] "4-40 nylon screw and mounting hole"
  round 8 hole 3.2: 1(0,0)
  body extent -3.3,-3.3 3.3,3.3, height 2.69
SOD-123 [mm] "On Semi recommended land pattern"
  rect 0.915x1.22 smd: 1(-1.637,0) 2(1.637,0)
  silkscreen extent -2.74,-1.17 2.03,1.17, body extent -1.93,-0.9 1.93,0.9, height 1.35
SOD-323 [mm] "NXP recommended land pattern"
  rect 0.6x0.6 smd paste-0.05: 1(-1.1,0) 2(1.1,0)
  silkscreen extent -2.06,-0.86 1.53,0.86, body extent -1.3,-0.67 1.3,0.68, height 1.1
SOT-23 [mm] "SOT23, 3-Leads, Body 2.9x1.3mm, Pitch 0.95mm, Lead Span 2.5mm, IPC Medium Density"
  rrect50% 1x0.6 smd: 1(-1.2,0.95) 2(-1.2,-0.95) 3(1.2,0)
  silkscreen extent -1.62,-1.5 0.7,1.5, body extent -1.16,-1.45 1.21,1.45, height 1
TE_282843-2 [mm] "Terminal Block, 10.16mm, 2x1, TH"
  rrect50% 2.1x2.1 hole 1.4: 1(-5.08,0)
  round 2.1 hole 1.4: 2(5.08,0)
  silkscreen extent -7.62,-5 8.12,4.5, body extent -7.62,-4.5 8.12,4.5, height 15.21
TERM_BLK_ED555-2DS [mil]
  rrect4% 100x100 hole 50: 1(0,0)
  round 100 hole 50: 2(138,0)
  silkscreen extent -93,-161 215,113, body extent -69,-150 207,106, height 323
WEEE_Minimum [mil] "WEEElie bin"
  silkscreen extent -95,-172 99,104

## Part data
C1 C16 C24 C25 C27 C31 C33 C34 C40 C45 C102: library part CMP-0079602-1, "CAP, CERM, 0.1 µF, 50 V,+/- 10%, X7R, AEC-Q200 Grade 1, 0603", Cap_Case=0603, Manufacturer=Kemet, Supplier Part Number 1=399-6856-1-ND, TempCo=X7R, Tolerance_%=10%, Value2=50V, ValueDisplayed=0.1µF
C2 C100: library part CMP-0090019-1, "Cap Alum 47UF 20% 500V Thruhole", Digikey Part Number=1189-4270-ND, Leakage Current=459.89uA, Manufacturer=Rubycon, Mouser Part Number=232-500LXW47MEFR18X2, Operating Temperature Range="-40°C to +105°C", Tolerance_%=20%, ValueDisplayed=47uF
C3 C4 C6 C7 C9 C10 C13 C14: library part CMP-0009140-1, "CAP, CERM, 0.1 uF, 630 V, +/- 10%, X7R, AEC-Q200 Grade 1, 1210", Cap_Case=1210, Manufacturer=TDK, Supplier Part Number 1=445-7116-1-ND, TempCo=X7R, Tolerance_%=10%, Value1=Unknown, Value2=630V, ValueDisplayed=0.1uF
C5 C23: library part CMP-0007415-4, "CAP, CERM, 0.22 uF, 25 V, +/- 10%, X7R, 0603", Cap_Case=0603, Manufacturer=MuRata, Supplier Part Number 1=490-3290-1-ND, TempCo=X7R, Tolerance_%=10%, Value1=Unknown, Value2=25V, ValueDisplayed=0.22uF
C8 C11: library part CMP-0088818-1, "1µF ±20% 630V Ceramic Capacitor X7T Stacked SMD, 2 J-Lead", Digikey Part Number=445-10515-1-ND, Manufacturer=TDK, Mouser Part Number=810-CKG57NX7T2J105MJ, Operating Temperature Range="-55°C to +125°C", TempCo=+22/-33%, Temperature Characteristic=X7T, Tolerance_%=20%, ValueDisplayed=1uF
C12 C101: library part CMP-0089997-1, "120µF 450V Aluminum Electrolytic Capacitors Radial, Can 12000 Hrs @ 105°C", Digikey Part Number=565-4226-ND, Leakage Current=2260uA, Manufacturer="United Chemi-Con", Mouser Part Number=661-EKXJ451ELL12140S, Operating Temperature Range="-40°C to +105°C", Tolerance_%=20%, ValueDisplayed=120uF
C15 C17: library part CMP-0008992-2, "CAP, CERM, 1 uF, 50 V, +/- 10%, X7R, 1206", Cap_Case=1206, Manufacturer=MuRata, Supplier Part Number 1=GRM31MR71H105KA88L-ND, TempCo=X7R, Tolerance_%=10%, Value1=Unknown, Value2=50V, ValueDisplayed=1uF
C18: library part CMP-0007037-4, "CAP, CERM, 1 uF, 16 V, +/- 10%, X7R, 0603", Cap_Case=0603, Manufacturer=TDK, PartNumber=C1608X7R1C105K080AC, Supplier Part Number 1=445-1604-1-ND, TempCo=X7R, Tolerance_%=10%, Value1="0.0057 ohm", Value2=16V, ValueDisplayed=1uF
C19: library part CMP-0007050-4, "CAP, CERM, 0.47 uF, 50 V, +/- 10%, X7R, 0603", Cap_Case=0603, Manufacturer=TDK, PartNumber=C1608X7R1H474K080AC, Supplier Part Number 1=445-5952-1-ND, TempCo=X7R, Tolerance_%=10%, Value1="0.010974 ohm", Value2=50V, ValueDisplayed=0.47uF
C20 C36 C37 C42: library part CMP-0007405-2, "CAP, CERM, 1 uF, 25 V, +/- 10%, X7R, 0603", Cap_Case=0603, Manufacturer=MuRata, Supplier Part Number 1=490-5307-1-ND, TempCo=X7R, Tolerance_%=10%, Value1=Unknown, Value2=25V, ValueDisplayed=1uF
C21: library part CMP-0007171-4, "CAP, CERM, 100 pF, 50 V, +/- 5%, C0G/NP0, 0603", Cap_Case=0603, Manufacturer=MuRata, Supplier Part Number 1=490-1427-1-ND, TempCo=C0G/NP0, Tolerance_%=5%, Value1=Unknown, Value2=50V, ValueDisplayed=100pF
C22 C26 C30: library part CMP-0008967-2, "CAP, CERM, 4.7 uF, 25 V, +/- 10%, X7R, 1206", Cap_Case=1206, Manufacturer=MuRata, Supplier Part Number 1=490-1809-1-ND, TempCo=X7R, Tolerance_%=10%, Value1=Unknown, Value2=25V, ValueDisplayed=4.7uF
C28: library part CMP-0074691-1, "CAP, CERM, 22 µF, 10 V,+/- 10%, X7R, 1206", Cap_Case=1206, Manufacturer=MuRata, Supplier Part Number 1=490-10937-1-ND, TempCo=X7R, Tolerance_%=10%, Value2=10V, ValueDisplayed=22µF
C29 C32 C39: library part CMP-0007185-4, "CAP, CERM, 150 pF, 50 V, +/- 5%, C0G/NP0, 0603", Cap_Case=0603, Manufacturer=MuRata, Supplier Part Number 1=490-1431-1-ND, TempCo=C0G/NP0, Tolerance_%=5%, Value1=Unknown, Value2=50V, ValueDisplayed=150pF
C35: library part CMP-0007457-4, "CAP, CERM, 0.047 uF, 50 V, +/- 10%, X7R, 0603", Cap_Case=0603, Manufacturer=MuRata, Supplier Part Number 1=490-3287-1-ND, TempCo=X7R, Tolerance_%=10%, Value1=Unknown, Value2=50V, ValueDisplayed=0.047uF
C38 C44: library part CMP-0008346-2, "CAP, CERM, 4.7 uF, 25 V, +/- 10%, X7R, 0805", Cap_Case=0805, Manufacturer=MuRata, Supplier Part Number 1=490-9962-1-ND, TempCo=X7R, Tolerance_%=10%, Value1=Unknown, Value2=25V, ValueDisplayed=4.7uF
C41: library part CMP-0007170-2, "CAP, CERM, 10 pF, 50 V, +/- 5%, C0G/NP0, 0603", Cap_Case=0603, Manufacturer=MuRata, Supplier Part Number 1=490-1403-1-ND, TempCo=C0G/NP0, Tolerance_%=5%, Value1=Unknown, Value2=50V, ValueDisplayed=10pF
C43: library part CMP-0007050-2, "CAP, CERM, 0.47 uF, 50 V, +/- 10%, X7R, 0603", Cap_Case=0603, Manufacturer=TDK, Supplier Part Number 1=445-5952-1-ND, TempCo=X7R, Tolerance_%=10%, Value1="0.010974 ohm", Value2=50V, ValueDisplayed=0.47uF
D1: library part CMP-0087641-2, "Diode Silicon Carbide Schottky 1200V 9.5A (DC) Through Hole TO-220-2", Manufacturer=Cree
D2 D3: library part CMP-0028525-2, "Diode, Schottky, 30 V, 0.5 A, SOD-123", Manufacturer="ON Semiconductor", Value1=0.5A, Value2=0.43V
D4 D6 D7 D9: library part CMP-0028455-2, "Diode, Schottky, 30 V, 0.2 A, SOD-323", Manufacturer="ON Semiconductor", Value1=0.2A, Value2=0.35V
D5 D8 D10: library part CMP-0005853-3, "Diode, Zener, 4.7 V, 200 mW, SOD-323", Manufacturer="Diodes Inc.", Power_W=200mW, Value1=0.2W
H1: library part CMP-0089070-1, "Heat Sink TO-220 Aluminum  Board Level, Vertical", Manufacturer=Wakefield-Vette
H2: library part CMP-0004086-1, "Heat Sink, TO-247, TO-264, Vertical", Manufacturer="Wakefield Solutions"
H3 H4 H5 H6: library part CMP-0003617-1, "Machine Screw, Round, #4-40 x 1/4, Nylon, Philips panhead", Manufacturer="B&F Fastener Supply", Supplier Part Number 1=H542-ND
H7 H8 H9 H10: library part CMP-0003610-1, "Standoff, Hex, 0.5\"L #4-40 Nylon", Manufacturer=Keystone, Supplier Part Number 1=36-1902C-ND
J1 J2: library part CMP-0067665-1, "Terminal Block, 10.16mm, 2x1, Tin, TH", Color=Green, Current_A=17.5A, Manufacturer="TE Connectivity", Supplier Part Number 1=A98084-ND, Voltage_V=600V
J3 J6 J8: library part CMP-0002337-1, "Header, 100mil, 2x1, Tin, TH", Color=Black, Current_A=3A, Manufacturer="Sullins Connector Solutions", Supplier Part Number 1=S1012E-02-ND, Voltage_V=1.8kV
J4: library part CMP-0074913-1, "Terminal Block, 3.5mm Pitch, 2x1, TH", Color=Grey, Current_A=6A, Manufacturer="On-Shore Technology", Supplier Part Number 1=ED1514-ND, Voltage_V=150V
J5 J7: library part CMP-0002338-1, "Header, 100mil, 3x1, Tin, TH", Color=Black, Current_A=3A, Manufacturer="Sullins Connector Solutions", Supplier Part Number 1=S1012E-03-ND, Voltage_V=1.8kV
L1: library part CMP-0059589-1, "Inductor, Wirewound, Ceramic, 10 uH, 0.48 A, 0.36 ohm, SMD", Manufacturer="Taiyo Yuden", Supplier Part Number 1=587-1613-1-ND, Value1="0.36 ohm", Value2=0.48A, ValueDisplayed=10uH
